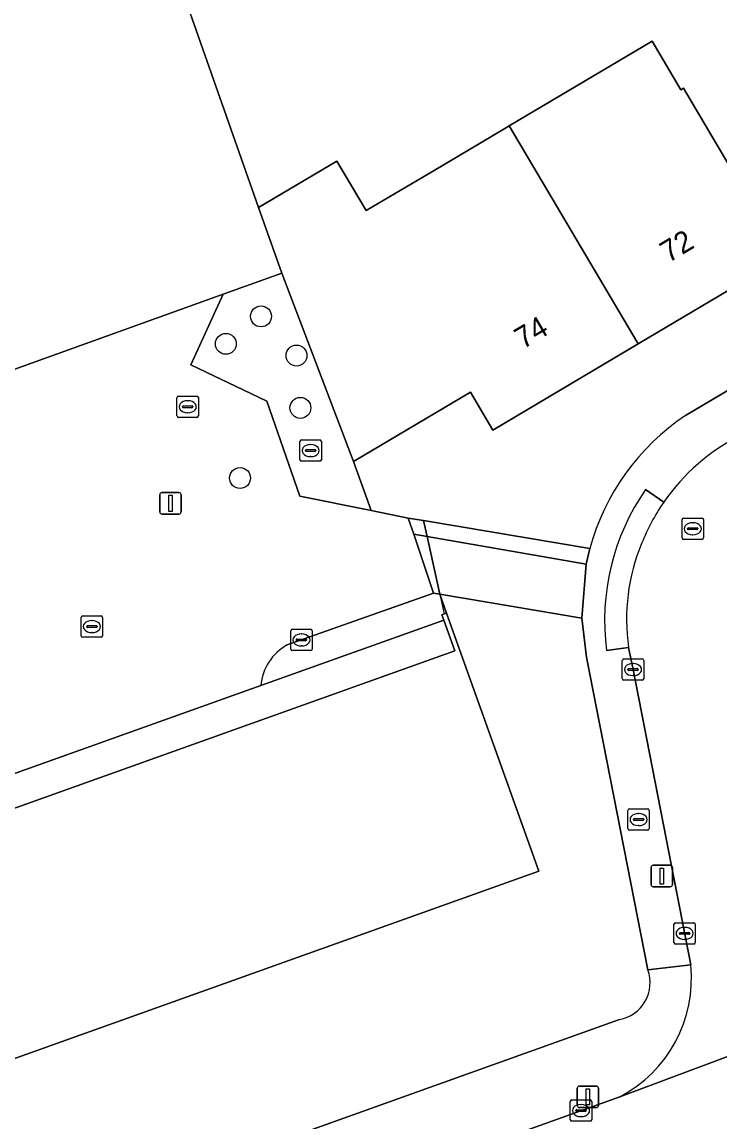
# Model space of a CAD drawing. Extents: x 159499 to 160349, y 382524 to 383273.
# Drawn here: x 159656.3 to 159688.9, y 382937.3 to 382988.7 of the extents above; entities that cross this region are included whole.
import ezdxf

# ---------------------------------------------------------------- set-up
doc = ezdxf.new("R2010")
doc.units = 0
for name, color, linetype in [('IMGEO_Boom', 7, 'Continuous'), ('IMGEO_Brandkraan', 7, 'Continuous'), ('IMGEO_Erf', 7, 'Continuous'), ('IMGEO_Grasland_overig', 7, 'Continuous'), ('IMGEO_Groenvoorziening', 7, 'Continuous'), ('IMGEO_Hek', 7, 'Continuous'), ('IMGEO_Kolk', 7, 'Continuous'), ('IMGEO_Lichtmast', 7, 'Continuous'), ('IMGEO_Pand', 7, 'Continuous'), ('IMGEO_Pand_nummerreeks', 7, 'Continuous'), ('IMGEO_Parkeervlak_open', 7, 'Continuous'), ('IMGEO_Rijbaan_lokaal_open', 7, 'Continuous'), ('IMGEO_Rioolput', 7, 'Continuous'), ('IMGEO_Voetpad_open', 7, 'Continuous')]:
    doc.layers.add(name, color=color, linetype=linetype)

msp = doc.modelspace()

# ---------------------------------------------------------------- linework, layer by layer
at = {"layer": 'IMGEO_Boom'}
for centre in [(159667.462, 382974.908), (159665.819, 382973.625), (159669.12, 382973.079), (159669.302, 382970.634), (159666.481, 382967.357)]:
    msp.add_circle(centre, 0.489, dxfattribs=at)
at = {"layer": 'IMGEO_Brandkraan'}
for p, q in [((159684.602, 382950.974), (159684.602, 382951.826)), ((159684.677, 382951.9), (159685.529, 382951.9)), ((159685.603, 382951.826), (159685.603, 382950.974)), ((159684.861, 382951.394), (159684.861, 382951.406)), ((159685.299, 382951.357), (159684.901, 382951.357)), ((159684.904, 382951.443), (159685.302, 382951.443)), ((159685.09, 382951.68), (159685.115, 382951.68)), ((159685.345, 382951.406), (159685.345, 382951.394)), ((159685.529, 382950.9), (159684.677, 382950.9)), ((159685.113, 382951.12), (159685.088, 382951.12))]:
    msp.add_line(p, q, dxfattribs=at)
for points in [[(159684.602, 382950.974), (159684.602, 382951.826)], [(159684.677, 382951.9), (159685.529, 382951.9)], [(159685.603, 382951.826), (159685.603, 382950.974)], [(159685.529, 382950.9), (159684.677, 382950.9)]]:
    msp.add_lwpolyline(points, dxfattribs=at)
for centre, radius, start, end in [((159684.679, 382951.824), 0.0765, 91.552, 178.448), ((159684.679, 382951.824), 0.0765, 91.552, 178.448), ((159685.527, 382951.824), 0.0765, 1.552, 88.448), ((159685.527, 382951.824), 0.0765, 1.552, 88.448), ((159684.901, 382951.403), 0.0403, 85.8775, 175.7526), ((159684.898, 382951.393), 0.0366, 178.938, 274.7102), ((159685.302, 382951.4), 0.043, 264.8664, 352.4533), ((159685.306, 382951.405), 0.0386, 1.7309, 96.639), ((159684.679, 382950.976), 0.0765, 181.552, 268.448), ((159684.679, 382950.976), 0.0765, 181.552, 268.448), ((159685.527, 382950.976), 0.0765, 271.552, 358.448), ((159685.527, 382950.976), 0.0765, 271.552, 358.448)]:
    msp.add_arc(centre, radius, start, end, dxfattribs=at)
for centre, major_axis, ratio, start_param, end_param in [((159685.089, 382951.4), (-0.387, 0.002), 0.722429, 4.712389, 7.853982), ((159685.114, 382951.4), (-0.39, 0.002), 0.717154, 1.570796, 4.712389)]:
    msp.add_ellipse(centre, major_axis=major_axis, ratio=ratio, start_param=start_param, end_param=end_param, dxfattribs=at)
at = {"layer": 'IMGEO_Erf'}
for points in [[(159691.726, 383006.538), (159684.709, 383002.371), (159680.717, 383000), (159674.384, 382996.239), (159663.847, 382989.981), (159667.344, 382979.99), (159671.009, 382982.163), (159672.381, 382979.849), (159675.547, 382981.727), (159678.85, 382983.686), (159679.058, 382983.809), (159685.737, 382987.769), (159687.083, 382985.498), (159687.206, 382985.567), (159689.342, 382981.964)], [(159687.291, 382970.274), (159725.98, 382993.204)], [(159691.891, 382977.662), (159685.088, 382973.63), (159678.287, 382969.599), (159677.242, 382971.363), (159671.788, 382968.131), (159672.61, 382965.844), (159674.339, 382965.486), (159675.06, 382965.365), (159682.825, 382964.06)]]:
    msp.add_lwpolyline(points, dxfattribs=at)
msp.add_arc((159693.347, 382961.21), 10.901, 123.7474, 164.843, dxfattribs=at)
at = {"layer": 'IMGEO_Grasland_overig'}
for points in [[(159675.06, 382965.365), (159674.339, 382965.486), (159674.596, 382964.728), (159675.225, 382964.619)], [(159682.825, 382964.06), (159675.06, 382965.365), (159675.225, 382964.619), (159682.655, 382963.335)], [(159675.225, 382964.619), (159674.596, 382964.728), (159675.525, 382961.982), (159675.818, 382961.931)], [(159682.655, 382963.335), (159675.225, 382964.619), (159675.818, 382961.931), (159682.454, 382960.802)]]:
    msp.add_lwpolyline(points, close=True, dxfattribs=at)
at = {"layer": 'IMGEO_Groenvoorziening'}
msp.add_lwpolyline([(159665.691, 382975.944), (159664.183, 382972.651), (159667.737, 382970.948), (159669.28, 382966.514), (159672.61, 382965.844), (159671.788, 382968.131), (159668.441, 382976.932)], close=True, dxfattribs=at)
for points in [[(159685.537, 382944.38), (159682.676, 382958.981), (159682.454, 382960.802), (159675.818, 382961.931), (159676.134, 382961.046), (159680.442, 382948.993), (159609.134, 382923.507), (159606.674, 382930.391), (159601.595, 382928.556), (159605.894, 382916.702)], [(159610.141, 382915.546), (159684.209, 382942.053)]]:
    msp.add_lwpolyline(points, dxfattribs=at)
msp.add_arc((159683.883, 382943.781), 1.759, 280.6741, 19.8998, dxfattribs=at)
at = {"layer": 'IMGEO_Hek'}
for points in [[(159675.06, 382965.365), (159675.225, 382964.619)], [(159675.225, 382964.619), (159675.818, 382961.931)], [(159675.818, 382961.931), (159676.022, 382961.006)]]:
    msp.add_lwpolyline(points, dxfattribs=at)
at = {"layer": 'IMGEO_Kolk'}
for p, q in [((159663.536, 382970.26), (159663.536, 382971.112)), ((159663.611, 382971.186), (159664.463, 382971.186)), ((159664.024, 382970.966), (159664.049, 382970.966)), ((159664.537, 382971.112), (159664.537, 382970.26)), ((159663.795, 382970.68), (159663.795, 382970.692)), ((159664.233, 382970.643), (159663.835, 382970.643)), ((159663.838, 382970.729), (159664.236, 382970.729)), ((159664.047, 382970.406), (159664.022, 382970.406)), ((159664.279, 382970.692), (159664.279, 382970.68)), ((159664.463, 382970.186), (159663.611, 382970.186)), ((159659.059, 382959.99), (159659.059, 382960.842)), ((159659.134, 382960.916), (159659.986, 382960.916)), ((159659.547, 382960.696), (159659.572, 382960.696)), ((159660.06, 382960.842), (159660.06, 382959.99)), ((159659.318, 382960.41), (159659.318, 382960.422)), ((159659.756, 382960.373), (159659.358, 382960.373)), ((159659.361, 382960.459), (159659.759, 382960.459)), ((159659.57, 382960.136), (159659.545, 382960.136)), ((159659.802, 382960.422), (159659.802, 382960.41)), ((159668.851, 382959.366), (159668.851, 382960.218)), ((159668.926, 382960.292), (159669.778, 382960.292)), ((159669.339, 382960.072), (159669.364, 382960.072)), ((159669.852, 382960.218), (159669.852, 382959.366)), ((159659.986, 382959.916), (159659.134, 382959.916)), ((159669.11, 382959.786), (159669.11, 382959.798)), ((159669.548, 382959.749), (159669.15, 382959.749)), ((159669.153, 382959.835), (159669.551, 382959.835)), ((159669.362, 382959.512), (159669.337, 382959.512)), ((159669.594, 382959.798), (159669.594, 382959.786)), ((159669.778, 382959.292), (159668.926, 382959.292)), ((159684.343, 382957.982), (159684.343, 382958.834)), ((159684.418, 382958.908), (159685.27, 382958.908)), ((159684.645, 382958.451), (159685.043, 382958.451)), ((159684.831, 382958.688), (159684.856, 382958.688)), ((159685.344, 382958.834), (159685.344, 382957.982)), ((159684.602, 382958.402), (159684.602, 382958.414)), ((159685.04, 382958.365), (159684.642, 382958.365)), ((159684.854, 382958.128), (159684.829, 382958.128)), ((159685.086, 382958.414), (159685.086, 382958.402)), ((159685.27, 382957.908), (159684.418, 382957.908)), ((159686.751, 382945.654), (159686.751, 382946.506)), ((159686.826, 382946.58), (159687.678, 382946.58)), ((159687.053, 382946.123), (159687.451, 382946.123)), ((159687.239, 382946.36), (159687.264, 382946.36)), ((159687.752, 382946.506), (159687.752, 382945.654)), ((159687.678, 382945.58), (159686.826, 382945.58)), ((159687.01, 382946.074), (159687.01, 382946.086)), ((159687.448, 382946.037), (159687.05, 382946.037)), ((159687.262, 382945.8), (159687.237, 382945.8)), ((159687.494, 382946.086), (159687.494, 382946.074)), ((159681.913, 382937.376), (159681.913, 382938.228)), ((159681.988, 382938.302), (159682.84, 382938.302)), ((159682.401, 382938.082), (159682.426, 382938.082)), ((159682.914, 382938.228), (159682.914, 382937.376)), ((159682.172, 382937.796), (159682.172, 382937.808)), ((159682.61, 382937.759), (159682.212, 382937.759)), ((159682.215, 382937.845), (159682.613, 382937.845)), ((159682.424, 382937.522), (159682.399, 382937.522)), ((159682.656, 382937.808), (159682.656, 382937.796)), ((159682.84, 382937.302), (159681.988, 382937.302))]:
    msp.add_line(p, q, dxfattribs=at)
for points in [[(159663.536, 382970.26), (159663.536, 382971.112)], [(159663.611, 382971.186), (159664.463, 382971.186)], [(159664.537, 382971.112), (159664.537, 382970.26)], [(159664.463, 382970.186), (159663.611, 382970.186)], [(159659.059, 382959.99), (159659.059, 382960.842)], [(159659.134, 382960.916), (159659.986, 382960.916)], [(159660.06, 382960.842), (159660.06, 382959.99)], [(159668.851, 382959.366), (159668.851, 382960.218)], [(159668.926, 382960.292), (159669.778, 382960.292)], [(159669.852, 382960.218), (159669.852, 382959.366)], [(159659.986, 382959.916), (159659.134, 382959.916)], [(159669.778, 382959.292), (159668.926, 382959.292)], [(159684.343, 382957.982), (159684.343, 382958.834)], [(159684.418, 382958.908), (159685.27, 382958.908)], [(159685.344, 382958.834), (159685.344, 382957.982)], [(159685.27, 382957.908), (159684.418, 382957.908)], [(159686.751, 382945.654), (159686.751, 382946.506)], [(159686.826, 382946.58), (159687.678, 382946.58)], [(159687.752, 382946.506), (159687.752, 382945.654)], [(159687.678, 382945.58), (159686.826, 382945.58)], [(159681.913, 382937.376), (159681.913, 382938.228)], [(159681.988, 382938.302), (159682.84, 382938.302)], [(159682.914, 382938.228), (159682.914, 382937.376)], [(159682.84, 382937.302), (159681.988, 382937.302)]]:
    msp.add_lwpolyline(points, dxfattribs=at)
for centre, radius, start, end in [((159663.613, 382971.11), 0.0765, 91.552, 178.448), ((159663.613, 382971.11), 0.0765, 91.552, 178.448), ((159664.461, 382971.11), 0.0765, 1.552, 88.448), ((159664.461, 382971.11), 0.0765, 1.552, 88.448), ((159663.613, 382970.262), 0.0765, 181.552, 268.448), ((159663.613, 382970.262), 0.0765, 181.552, 268.448), ((159663.835, 382970.689), 0.0403, 85.8775, 175.7526), ((159663.832, 382970.679), 0.0366, 178.938, 274.7102), ((159664.236, 382970.686), 0.043, 264.8664, 352.4533), ((159664.24, 382970.691), 0.0386, 1.7309, 96.639), ((159664.461, 382970.262), 0.0765, 271.552, 358.448), ((159664.461, 382970.262), 0.0765, 271.552, 358.448), ((159659.136, 382960.84), 0.0765, 91.552, 178.448), ((159659.136, 382960.84), 0.0765, 91.552, 178.448), ((159659.984, 382960.84), 0.0765, 1.552, 88.448), ((159659.984, 382960.84), 0.0765, 1.552, 88.448), ((159659.136, 382959.992), 0.0765, 181.552, 268.448), ((159659.136, 382959.992), 0.0765, 181.552, 268.448), ((159659.358, 382960.419), 0.0403, 85.8775, 175.7526), ((159659.355, 382960.409), 0.0366, 178.938, 274.7102), ((159659.759, 382960.416), 0.043, 264.8664, 352.4533), ((159659.763, 382960.421), 0.0386, 1.7309, 96.639), ((159659.984, 382959.992), 0.0765, 271.552, 358.448), ((159659.984, 382959.992), 0.0765, 271.552, 358.448), ((159668.928, 382960.216), 0.0765, 91.552, 178.448), ((159668.928, 382960.216), 0.0765, 91.552, 178.448), ((159669.776, 382960.216), 0.0765, 1.552, 88.448), ((159669.776, 382960.216), 0.0765, 1.552, 88.448), ((159669.15, 382959.795), 0.0403, 85.8775, 175.7526), ((159669.147, 382959.785), 0.0366, 178.938, 274.7102), ((159669.551, 382959.792), 0.043, 264.8664, 352.4533), ((159669.555, 382959.797), 0.0386, 1.7309, 96.639), ((159668.928, 382959.368), 0.0765, 181.552, 268.448), ((159668.928, 382959.368), 0.0765, 181.552, 268.448), ((159669.776, 382959.368), 0.0765, 271.552, 358.448), ((159669.776, 382959.368), 0.0765, 271.552, 358.448), ((159684.42, 382958.832), 0.0765, 91.552, 178.448), ((159684.42, 382958.832), 0.0765, 91.552, 178.448), ((159684.642, 382958.411), 0.0403, 85.8775, 175.7526), ((159685.047, 382958.413), 0.0386, 1.7309, 96.639), ((159685.268, 382958.832), 0.0765, 1.552, 88.448), ((159685.268, 382958.832), 0.0765, 1.552, 88.448), ((159684.42, 382957.984), 0.0765, 181.552, 268.448), ((159684.42, 382957.984), 0.0765, 181.552, 268.448), ((159684.639, 382958.401), 0.0366, 178.938, 274.7102), ((159685.043, 382958.408), 0.043, 264.8664, 352.4533), ((159685.268, 382957.984), 0.0765, 271.552, 358.448), ((159685.268, 382957.984), 0.0765, 271.552, 358.448), ((159686.828, 382946.504), 0.0765, 91.552, 178.448), ((159686.828, 382946.504), 0.0765, 91.552, 178.448), ((159687.05, 382946.083), 0.0403, 85.8775, 175.7526), ((159687.455, 382946.085), 0.0386, 1.7309, 96.639), ((159687.676, 382946.504), 0.0765, 1.552, 88.448), ((159687.676, 382946.504), 0.0765, 1.552, 88.448), ((159686.828, 382945.656), 0.0765, 181.552, 268.448), ((159686.828, 382945.656), 0.0765, 181.552, 268.448), ((159687.047, 382946.073), 0.0366, 178.938, 274.7102), ((159687.451, 382946.08), 0.043, 264.8664, 352.4533), ((159687.676, 382945.656), 0.0765, 271.552, 358.448), ((159687.676, 382945.656), 0.0765, 271.552, 358.448), ((159681.99, 382938.226), 0.0765, 91.552, 178.448), ((159681.99, 382938.226), 0.0765, 91.552, 178.448), ((159682.838, 382938.226), 0.0765, 1.552, 88.448), ((159682.838, 382938.226), 0.0765, 1.552, 88.448), ((159681.99, 382937.378), 0.0765, 181.552, 268.448), ((159681.99, 382937.378), 0.0765, 181.552, 268.448), ((159682.212, 382937.805), 0.0403, 85.8775, 175.7526), ((159682.209, 382937.795), 0.0366, 178.938, 274.7102), ((159682.613, 382937.802), 0.043, 264.8664, 352.4533), ((159682.617, 382937.807), 0.0386, 1.7309, 96.639), ((159682.838, 382937.378), 0.0765, 271.552, 358.448), ((159682.838, 382937.378), 0.0765, 271.552, 358.448)]:
    msp.add_arc(centre, radius, start, end, dxfattribs=at)
for centre, major_axis, ratio, start_param, end_param in [((159664.023, 382970.686), (-0.387, 0.002), 0.722429, 4.712389, 7.853982), ((159664.048, 382970.686), (-0.39, 0.002), 0.717154, 1.570796, 4.712389), ((159659.546, 382960.416), (-0.387, 0.002), 0.722429, 4.712389, 7.853982), ((159659.571, 382960.416), (-0.39, 0.002), 0.717154, 1.570796, 4.712389), ((159669.338, 382959.792), (-0.387, 0.002), 0.722429, 4.712389, 7.853982), ((159669.363, 382959.792), (-0.39, 0.002), 0.717154, 1.570796, 4.712389), ((159684.83, 382958.408), (-0.387, 0.002), 0.722429, 4.712389, 7.853982), ((159684.855, 382958.408), (-0.39, 0.002), 0.717154, 1.570796, 4.712389), ((159687.238, 382946.08), (-0.387, 0.002), 0.722429, 4.712389, 7.853982), ((159687.263, 382946.08), (-0.39, 0.002), 0.717154, 1.570796, 4.712389), ((159682.4, 382937.802), (-0.387, 0.002), 0.722429, 4.712389, 7.853982), ((159682.425, 382937.802), (-0.39, 0.002), 0.717154, 1.570796, 4.712389)]:
    msp.add_ellipse(centre, major_axis=major_axis, ratio=ratio, start_param=start_param, end_param=end_param, dxfattribs=at)
at = {"layer": 'IMGEO_Lichtmast'}
for p, q in [((159662.834, 382966.673), (159663.624, 382966.673)), ((159663.624, 382966.673), (159662.834, 382966.673)), ((159662.734, 382965.773), (159662.734, 382966.573)), ((159662.734, 382966.573), (159662.734, 382965.773)), ((159663.724, 382966.573), (159663.724, 382965.773)), ((159663.724, 382965.773), (159663.724, 382966.573)), ((159663.624, 382965.673), (159662.834, 382965.673)), ((159662.834, 382965.673), (159663.624, 382965.673)), ((159685.79, 382949.261), (159686.58, 382949.261)), ((159686.58, 382949.261), (159685.79, 382949.261)), ((159685.69, 382948.361), (159685.69, 382949.161)), ((159685.69, 382949.161), (159685.69, 382948.361)), ((159686.68, 382949.161), (159686.68, 382948.361)), ((159686.68, 382948.361), (159686.68, 382949.161)), ((159686.58, 382948.261), (159685.79, 382948.261)), ((159685.79, 382948.261), (159686.58, 382948.261)), ((159682.34, 382938.945), (159683.13, 382938.945)), ((159683.13, 382938.945), (159682.34, 382938.945)), ((159682.24, 382938.045), (159682.24, 382938.845)), ((159682.24, 382938.845), (159682.24, 382938.045)), ((159683.23, 382938.845), (159683.23, 382938.045)), ((159683.23, 382938.045), (159683.23, 382938.845)), ((159683.13, 382937.945), (159682.34, 382937.945)), ((159682.34, 382937.945), (159683.13, 382937.945))]:
    msp.add_line(p, q, dxfattribs=at)
for points in [[(159663.154, 382966.548), (159663.304, 382966.548), (159663.304, 382965.798), (159663.154, 382965.798), (159663.154, 382966.548)], [(159686.11, 382949.136), (159686.26, 382949.136), (159686.26, 382948.386), (159686.11, 382948.386), (159686.11, 382949.136)], [(159682.66, 382938.82), (159682.81, 382938.82), (159682.81, 382938.07), (159682.66, 382938.07), (159682.66, 382938.82)]]:
    msp.add_lwpolyline(points, dxfattribs=at)
for centre, start, end in [((159662.834, 382966.573), 90, 180), ((159662.834, 382966.573), 90, 180), ((159663.624, 382966.573), 0, 90), ((159663.624, 382966.573), 360, 90), ((159662.834, 382965.773), 180, 270), ((159662.834, 382965.773), 180, 270), ((159663.624, 382965.773), 270, 0), ((159663.624, 382965.773), 270, 0), ((159685.79, 382949.161), 90, 180), ((159685.79, 382949.161), 90, 180), ((159686.58, 382949.161), 0, 90), ((159686.58, 382949.161), 360, 90), ((159685.79, 382948.361), 180, 270), ((159685.79, 382948.361), 180, 270), ((159686.58, 382948.361), 270, 0), ((159686.58, 382948.361), 270, 0), ((159682.34, 382938.845), 90, 180), ((159682.34, 382938.845), 90, 180), ((159683.13, 382938.845), 0, 90), ((159683.13, 382938.845), 360, 90), ((159682.34, 382938.045), 180, 270), ((159682.34, 382938.045), 180, 270), ((159683.13, 382938.045), 270, 0), ((159683.13, 382938.045), 270, 0)]:
    msp.add_arc(centre, 0.1, start, end, dxfattribs=at)
at = {"layer": 'IMGEO_Pand'}
for points in [[(159663.847, 382989.981), (159657.898, 383000), (159653.631, 383007.187), (159644.178, 383001.574), (159646.481, 382997.695), (159647.452, 382998.271), (159655.211, 382985.203), (159650.661, 382982.501), (159642.929, 382995.586), (159640.635, 382999.47), (159632.4, 382994.581), (159647.373, 382969.363), (159665.691, 382975.944), (159668.441, 382976.932), (159667.344, 382979.99)], [(159679.058, 382983.809), (159685.088, 382973.63), (159691.891, 382977.662), (159689.342, 382981.964), (159687.206, 382985.567), (159687.083, 382985.498), (159685.737, 382987.769)], [(159679.058, 382983.809), (159678.85, 382983.686), (159675.547, 382981.727), (159672.381, 382979.849), (159671.009, 382982.163), (159667.344, 382979.99), (159668.441, 382976.932), (159671.788, 382968.131), (159677.242, 382971.363), (159678.287, 382969.599), (159685.088, 382973.63)], [(159622.779, 382941.693), (159621.91, 382944.124), (159621.758, 382944.07), (159613.077, 382940.968), (159614.525, 382937.123), (159605.702, 382933.97), (159605.077, 382935.718), (159604.805, 382935.62), (159604.862, 382935.46), (159606.674, 382930.391), (159609.134, 382923.507), (159680.442, 382948.993), (159676.134, 382961.046), (159676.022, 382961.006), (159675.913, 382960.967), (159676.004, 382960.713), (159676.516, 382959.279), (159624.918, 382940.838), (159623.292, 382940.257)]]:
    msp.add_lwpolyline(points, close=True, dxfattribs=at)
at = {"layer": 'IMGEO_Parkeervlak_open'}
for points in [[(159668.684, 382959.557), (159675.525, 382961.982), (159674.596, 382964.728), (159674.339, 382965.486), (159672.61, 382965.844), (159669.28, 382966.514), (159667.737, 382970.948), (159664.183, 382972.651), (159665.691, 382975.944), (159647.373, 382969.363), (159629.938, 382963.1), (159615.784, 382958.015)], [(159622.779, 382941.693), (159667.453, 382957.657)]]:
    msp.add_lwpolyline(points, dxfattribs=at)
msp.add_arc((159669.859, 382957.447), 2.415, 119.1138, 175.0082, dxfattribs=at)
at = {"layer": 'IMGEO_Rijbaan_lokaal_open'}
for points in [[(159684.636, 382959.438), (159684.846, 382958.404), (159687.541, 382944.607)], [(159698.96, 382943.953), (159684.231, 382938.452), (159658.894, 382929.37), (159661.264, 382922.76), (159663.986, 382923.732), (159669.682, 382925.77), (159670.727, 382926.129), (159684.439, 382931.051), (159696.099, 382935.301)], [(159684.231, 382938.452), (159698.96, 382943.953)]]:
    msp.add_lwpolyline(points, dxfattribs=at)
for centre, radius, start, end in [((159694.282, 382960.686), 9.733, 116.9748, 145.2702), ((159694.355, 382960.642), 9.819, 145.3009, 158.1365), ((159693.763, 382960.766), 9.223, 157.4832, 188.2784), ((159681.353, 382943.967), 6.221, 297.5591, 5.9005)]:
    msp.add_arc(centre, radius, start, end, dxfattribs=at)
at = {"layer": 'IMGEO_Rioolput'}
for p, q in [((159669.28, 382968.213), (159669.28, 382969.065)), ((159669.355, 382969.139), (159670.207, 382969.139)), ((159669.768, 382968.919), (159669.793, 382968.919)), ((159670.281, 382969.065), (159670.281, 382968.213)), ((159669.539, 382968.633), (159669.539, 382968.645)), ((159669.977, 382968.596), (159669.579, 382968.596)), ((159669.582, 382968.682), (159669.98, 382968.682)), ((159669.791, 382968.359), (159669.766, 382968.359)), ((159670.023, 382968.645), (159670.023, 382968.633)), ((159670.207, 382968.139), (159669.355, 382968.139)), ((159687.133, 382964.561), (159687.133, 382965.413)), ((159687.208, 382965.487), (159688.06, 382965.487)), ((159687.621, 382965.267), (159687.646, 382965.267)), ((159688.134, 382965.413), (159688.134, 382964.561)), ((159687.392, 382964.981), (159687.392, 382964.993)), ((159687.83, 382964.944), (159687.432, 382964.944)), ((159687.435, 382965.03), (159687.833, 382965.03)), ((159687.644, 382964.707), (159687.619, 382964.707)), ((159687.876, 382964.993), (159687.876, 382964.981)), ((159688.06, 382964.487), (159687.208, 382964.487))]:
    msp.add_line(p, q, dxfattribs=at)
for points in [[(159669.28, 382968.213), (159669.28, 382969.065)], [(159669.355, 382969.139), (159670.207, 382969.139)], [(159670.281, 382969.065), (159670.281, 382968.213)], [(159670.207, 382968.139), (159669.355, 382968.139)], [(159687.133, 382964.561), (159687.133, 382965.413)], [(159687.208, 382965.487), (159688.06, 382965.487)], [(159688.134, 382965.413), (159688.134, 382964.561)], [(159688.06, 382964.487), (159687.208, 382964.487)]]:
    msp.add_lwpolyline(points, dxfattribs=at)
for centre, radius, start, end in [((159669.357, 382969.063), 0.0765, 91.552, 178.448), ((159669.357, 382969.063), 0.0765, 91.552, 178.448), ((159670.205, 382969.063), 0.0765, 1.552, 88.448), ((159670.205, 382969.063), 0.0765, 1.552, 88.448), ((159669.357, 382968.215), 0.0765, 181.552, 268.448), ((159669.357, 382968.215), 0.0765, 181.552, 268.448), ((159669.579, 382968.642), 0.0403, 85.8775, 175.7526), ((159669.576, 382968.632), 0.0366, 178.938, 274.7102), ((159669.98, 382968.639), 0.043, 264.8664, 352.4533), ((159669.984, 382968.644), 0.0386, 1.7309, 96.639), ((159670.205, 382968.215), 0.0765, 271.552, 358.448), ((159670.205, 382968.215), 0.0765, 271.552, 358.448), ((159687.21, 382965.411), 0.0765, 91.552, 178.448), ((159687.21, 382965.411), 0.0765, 91.552, 178.448), ((159688.058, 382965.411), 0.0765, 1.552, 88.448), ((159688.058, 382965.411), 0.0765, 1.552, 88.448), ((159687.432, 382964.99), 0.0403, 85.8775, 175.7526), ((159687.429, 382964.98), 0.0366, 178.938, 274.7102), ((159687.833, 382964.987), 0.043, 264.8664, 352.4533), ((159687.837, 382964.992), 0.0386, 1.7309, 96.639), ((159687.21, 382964.563), 0.0765, 181.552, 268.448), ((159687.21, 382964.563), 0.0765, 181.552, 268.448), ((159688.058, 382964.563), 0.0765, 271.552, 358.448), ((159688.058, 382964.563), 0.0765, 271.552, 358.448)]:
    msp.add_arc(centre, radius, start, end, dxfattribs=at)
for centre, major_axis, ratio, start_param, end_param in [((159669.767, 382968.639), (-0.387, 0.002), 0.722429, 4.712389, 7.853982), ((159669.792, 382968.639), (-0.39, 0.002), 0.717154, 1.570796, 4.712389), ((159687.62, 382964.987), (-0.387, 0.002), 0.722429, 4.712389, 7.853982), ((159687.645, 382964.987), (-0.39, 0.002), 0.717154, 1.570796, 4.712389)]:
    msp.add_ellipse(centre, major_axis=major_axis, ratio=ratio, start_param=start_param, end_param=end_param, dxfattribs=at)
at = {"layer": 'IMGEO_Voetpad_open'}
for points in [[(159725.98, 382993.204), (159687.291, 382970.274)], [(159685.429, 382966.824), (159686.283, 382966.231)], [(159686.283, 382966.231), (159685.429, 382966.824)], [(159682.825, 382964.06), (159682.655, 382963.335), (159682.454, 382960.802), (159682.676, 382958.981), (159685.537, 382944.38), (159687.541, 382944.607), (159684.846, 382958.404), (159684.636, 382959.438), (159683.605, 382959.302)], [(159676.004, 382960.713), (159675.913, 382960.967), (159676.022, 382961.006), (159676.134, 382961.046), (159675.818, 382961.931), (159675.525, 382961.982), (159668.684, 382959.557)], [(159667.453, 382957.657), (159676.004, 382960.713)], [(159683.605, 382959.302), (159684.636, 382959.438)], [(159687.541, 382944.607), (159685.537, 382944.38)], [(159684.209, 382942.053), (159610.141, 382915.546)], [(159610.022, 382911.818), (159612.644, 382912.722), (159648.081, 382925.494), (159654.498, 382927.794), (159658.894, 382929.37), (159684.231, 382938.452)]]:
    msp.add_lwpolyline(points, dxfattribs=at)
msp.add_lwpolyline([(159624.918, 382940.838), (159676.516, 382959.279), (159676.004, 382960.713), (159667.453, 382957.657), (159622.779, 382941.693), (159623.292, 382940.257)], close=True, dxfattribs=at)
for centre, radius, start, end in [((159693.347, 382961.21), 10.901, 123.7474, 164.843), ((159694.282, 382960.686), 9.733, 116.9748, 145.2702), ((159694.228, 382960.708), 10.715, 145.1978, 187.5413), ((159694.228, 382960.708), 10.715, 145.1978, 187.5413), ((159694.355, 382960.642), 9.819, 145.3009, 158.1365), ((159693.763, 382960.766), 9.223, 157.4832, 188.2784), ((159669.859, 382957.447), 2.415, 119.1138, 175.0082), ((159681.353, 382943.967), 6.221, 297.5591, 5.9005), ((159683.883, 382943.781), 1.759, 280.6741, 19.8998)]:
    msp.add_arc(centre, radius, start, end, dxfattribs=at)

# ---------------------------------------------------------------- texts
at = {"layer": 'IMGEO_Pand_nummerreeks'}
for s, p in [('72', (159686.491, 382977.391)), ('74', (159679.692, 382973.36))]:
    msp.add_text(s, height=1, rotation=30.6549, dxfattribs=at).set_placement(p)

doc.saveas('drawing.dxf')
